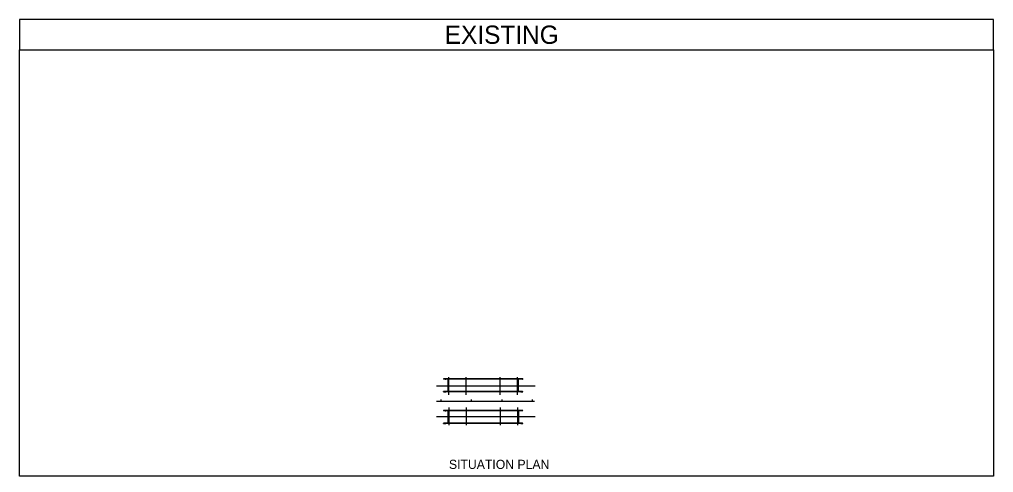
# Model space of a CAD drawing. Extents: x -6598 to 6602, y -3155 to 3145.
# Drawn here: x -6598 to -3398, y 1657 to 3145 of the extents above; entities that cross this region are included whole.
import ezdxf

# ---------------------------------------------------------------- set-up
doc = ezdxf.new("R2010")
doc.units = 0
for name, color, linetype in [('BridgeExistingStructure', 7, 'Continuous'), ('DsnShtMinorGrid01', 7, 'Continuous'), ('ShtPlotShapeBatchPrint', 7, 'Continuous')]:
    doc.layers.add(name, color=color, linetype=linetype)

msp = doc.modelspace()

# ---------------------------------------------------------------- linework, layer by layer
at = {"layer": 'BridgeExistingStructure'}
for p, q in [((-5205.5, 1964.9), (-5205.5, 1964.1)), ((-5205.5, 1964.9), (-5198.1, 1964.9)), ((-5203.5, 1963.6), (-5205.5, 1964.1)), ((-5198.1, 1965.1), (-5205.1, 1965.1)), ((-5205.1, 1965.1), (-5205.1, 1964.9)), ((-5188.4, 1963.6), (-5203.5, 1963.6)), ((-5199.8, 1963.6), (-5198.1, 1963.4)), ((-5188.4, 1965.1), (-5198.1, 1965.1)), ((-5198.1, 1964.8), (-5198.1, 1964.9)), ((-5188.4, 1964.8), (-5198.1, 1964.8)), ((-5188.4, 1963.4), (-5198.1, 1963.4)), ((-5190.4, 1923.4), (-5190.4, 1963.4)), ((-5189.8, 1963.4), (-5189.8, 1923.4)), ((-5188.4, 1921.8), (-5188.4, 1965.1)), ((-5188.3, 1921.8), (-5188.3, 1965.1)), ((-4961.6, 1965.1), (-5188.3, 1965.1)), ((-4961.6, 1964.8), (-5188.3, 1964.8)), ((-4961.6, 1963.6), (-5188.3, 1963.6)), ((-4961.6, 1963.4), (-5188.3, 1963.4)), ((-4961.6, 1921.8), (-4961.6, 1965.1)), ((-4951.7, 1965.1), (-4961.4, 1965.1)), ((-4961.4, 1921.8), (-4961.4, 1965.1)), ((-4951.7, 1964.8), (-4961.4, 1964.8)), ((-4946.3, 1963.6), (-4961.4, 1963.6)), ((-4951.7, 1963.4), (-4961.4, 1963.4)), ((-4960.1, 1923.4), (-4960.1, 1963.4)), ((-4959.4, 1923.4), (-4959.4, 1963.4)), ((-4951.7, 1965.1), (-4944.7, 1965.1)), ((-4944.3, 1964.9), (-4951.7, 1964.9)), ((-4951.7, 1964.8), (-4951.7, 1964.9)), ((-4950, 1963.6), (-4951.7, 1963.4)), ((-4946.3, 1963.6), (-4944.3, 1964.1)), ((-4944.7, 1965.1), (-4944.7, 1964.9)), ((-4944.3, 1964.9), (-4944.3, 1964.1)), ((-5203.5, 1923.3), (-5205.5, 1922.8)), ((-5205.5, 1921.9), (-5205.5, 1922.8)), ((-5205.5, 1921.9), (-5198.1, 1921.9)), ((-5205.1, 1921.8), (-5205.1, 1921.9)), ((-5198.1, 1921.8), (-5205.1, 1921.8)), ((-5188.4, 1923.3), (-5203.5, 1923.3)), ((-5199.8, 1923.3), (-5198.1, 1923.4)), ((-5188.4, 1923.4), (-5198.1, 1923.4)), ((-5188.4, 1922.4), (-5198.1, 1922.4)), ((-5198.1, 1922.4), (-5198.1, 1921.9)), ((-5188.4, 1921.8), (-5198.1, 1921.8)), ((-4961.6, 1923.4), (-5188.3, 1923.4)), ((-4961.6, 1923.3), (-5188.3, 1923.3)), ((-4961.6, 1922.4), (-5188.3, 1922.4)), ((-4961.6, 1921.8), (-5188.3, 1921.8)), ((-4951.7, 1923.4), (-4961.4, 1923.4)), ((-4946.3, 1923.3), (-4961.4, 1923.3)), ((-4951.7, 1922.4), (-4961.4, 1922.4)), ((-4951.7, 1921.8), (-4961.4, 1921.8)), ((-4950, 1923.3), (-4951.7, 1923.4)), ((-4951.7, 1922.4), (-4951.7, 1921.9)), ((-4944.3, 1921.9), (-4951.7, 1921.9)), ((-4951.7, 1921.8), (-4944.7, 1921.8)), ((-4946.3, 1923.3), (-4944.3, 1922.8)), ((-4944.7, 1921.8), (-4944.7, 1921.9)), ((-4944.3, 1921.9), (-4944.3, 1922.8)), ((-5205.5, 1860.9), (-5205.5, 1860.1)), ((-5205.5, 1860.9), (-5198.1, 1860.9)), ((-5203.5, 1859.6), (-5205.5, 1860.1)), ((-5198.1, 1861.1), (-5205.1, 1861.1)), ((-5205.1, 1861.1), (-5205.1, 1860.9)), ((-5188.4, 1859.6), (-5203.5, 1859.6)), ((-5199.8, 1859.6), (-5198.1, 1859.4)), ((-5188.4, 1861.1), (-5198.1, 1861.1)), ((-5198.1, 1860.4), (-5198.1, 1860.9)), ((-5188.4, 1860.4), (-5198.1, 1860.4)), ((-5188.4, 1859.4), (-5198.1, 1859.4)), ((-5190.4, 1859.4), (-5190.4, 1819.4)), ((-5189.8, 1819.4), (-5189.8, 1859.4)), ((-5188.4, 1861.1), (-5188.4, 1817.8)), ((-5188.3, 1861.1), (-5188.3, 1817.8)), ((-4961.6, 1861.1), (-5188.3, 1861.1)), ((-4961.6, 1860.4), (-5188.3, 1860.4)), ((-4961.6, 1859.6), (-5188.3, 1859.6)), ((-4961.6, 1859.4), (-5188.3, 1859.4)), ((-4961.6, 1861.1), (-4961.6, 1817.8)), ((-4951.7, 1861.1), (-4961.4, 1861.1)), ((-4961.4, 1861.1), (-4961.4, 1817.8)), ((-4951.7, 1860.4), (-4961.4, 1860.4)), ((-4946.3, 1859.6), (-4961.4, 1859.6)), ((-4951.7, 1859.4), (-4961.4, 1859.4)), ((-4960.1, 1859.4), (-4960.1, 1819.4)), ((-4959.4, 1859.4), (-4959.4, 1819.4)), ((-4951.7, 1861.1), (-4944.7, 1861.1)), ((-4944.3, 1860.9), (-4951.7, 1860.9)), ((-4951.7, 1860.4), (-4951.7, 1860.9)), ((-4950, 1859.6), (-4951.7, 1859.4)), ((-4946.3, 1859.6), (-4944.3, 1860.1)), ((-4944.7, 1861.1), (-4944.7, 1860.9)), ((-4944.3, 1860.9), (-4944.3, 1860.1)), ((-5203.5, 1819.3), (-5205.5, 1818.8)), ((-5205.5, 1817.9), (-5205.5, 1818.8)), ((-5205.5, 1817.9), (-5198.1, 1817.9)), ((-5205.1, 1817.8), (-5205.1, 1817.9)), ((-5198.1, 1817.8), (-5205.1, 1817.8)), ((-5188.4, 1819.3), (-5203.5, 1819.3)), ((-5199.8, 1819.3), (-5198.1, 1819.4)), ((-5188.4, 1819.4), (-5198.1, 1819.4)), ((-5188.4, 1818.1), (-5198.1, 1818.1)), ((-5198.1, 1818.1), (-5198.1, 1817.9)), ((-5188.4, 1817.8), (-5198.1, 1817.8)), ((-4961.6, 1819.4), (-5188.3, 1819.4)), ((-4961.6, 1819.3), (-5188.3, 1819.3)), ((-4961.6, 1818.1), (-5188.3, 1818.1)), ((-4961.6, 1817.8), (-5188.3, 1817.8)), ((-4951.7, 1819.4), (-4961.4, 1819.4)), ((-4946.3, 1819.3), (-4961.4, 1819.3)), ((-4951.7, 1818.1), (-4961.4, 1818.1)), ((-4951.7, 1817.8), (-4961.4, 1817.8)), ((-4950, 1819.3), (-4951.7, 1819.4)), ((-4951.7, 1818.1), (-4951.7, 1817.9)), ((-4944.3, 1817.9), (-4951.7, 1817.9)), ((-4951.7, 1817.8), (-4944.7, 1817.8)), ((-4946.3, 1819.3), (-4944.3, 1818.8)), ((-4944.7, 1817.8), (-4944.7, 1817.9)), ((-4944.3, 1817.9), (-4944.3, 1818.8))]:
    msp.add_line(p, q, dxfattribs=at)
at = {"layer": 'DsnShtMinorGrid01'}
for p, q in [((-5228.7, 1941.4), (-4904, 1941.4)), ((-5228.7, 1891.4), (-4906.6, 1891.4)), ((-5214.2, 1896.4), (-5214.2, 1891.4)), ((-5114.2, 1896.4), (-5114.2, 1891.4)), ((-5014.2, 1896.4), (-5014.2, 1891.4)), ((-4914.2, 1896.4), (-4914.2, 1891.4)), ((-5228.7, 1841.4), (-4904, 1841.4))]:
    msp.add_line(p, q, dxfattribs=at)
at = {"layer": 'ShtPlotShapeBatchPrint'}
for p, q in [((-5187.4, 1912.3), (-5187.4, 1970.5)), ((-5130.4, 1912.3), (-5130.4, 1970.5)), ((-5019.4, 1912.3), (-5019.4, 1970.5)), ((-4962.4, 1912.3), (-4962.4, 1970.5)), ((-5187.4, 1870.5), (-5187.4, 1812.3)), ((-5130.4, 1870.5), (-5130.4, 1812.3)), ((-5019.4, 1870.5), (-5019.4, 1812.3)), ((-4962.4, 1870.5), (-4962.4, 1812.3))]:
    msp.add_line(p, q, dxfattribs=at)
for points in [[(-6598.4, 3045.4), (-3398.4, 3045.4), (-3398.4, 3145.4), (-6598.4, 3145.4)], [(-6598.4, 3045.4), (-3398.4, 3045.4), (-3398.4, 1645.4), (-6598.4, 1645.4)]]:
    msp.add_lwpolyline(points, close=True, dxfattribs=at)

# ---------------------------------------------------------------- texts
for s, height, p in [('EXISTING', 60, (-5201.3, 3065.4)), ('SITUATION PLAN', 30, (-5187.5, 1668.7))]:
    msp.add_text(s, height=height, dxfattribs=at).set_placement(p)

doc.saveas('drawing.dxf')
